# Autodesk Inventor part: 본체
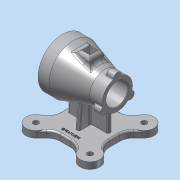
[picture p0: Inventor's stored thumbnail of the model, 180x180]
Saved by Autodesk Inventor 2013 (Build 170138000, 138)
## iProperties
Created: 2018-03
Part Number: 본체
Material: 알루미늄 6061
Document SubType Name: Modeling
Designer: dgall
Density: 2.71 g/cm^3
Mass: 1013.63 g
Surface Area: 870.735 cm^2
Volume: 374.034 cm^3
Author: dgall
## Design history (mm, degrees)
sketch "스케치1"
  geometry: L1 (0, 0)-(-68.205, 68.205); L2 (0, 0)-(-76.473, 0); L3 (-35.239, 60.483)-(-27.078, 52.322); L4 (-60.483, 35.239)-(-52.322, 27.078); L5 (-35.239, -60.483)-(-27.078, -52.322); L6 (-60.483, -35.239)-(-52.322, -27.078); L7 (0, 0)-(0, -76.473); L8 (0, 0)-(-68.205, -68.205); L9 (60.483, -35.239)-(52.322, -27.078); L10 (35.239, -60.483)-(27.078, -52.322); L11 (0, 0)-(76.473, 0); L12 (0, 0)-(68.205, -68.205); L13 (35.239, 60.483)-(27.078, 52.322); L14 (60.483, 35.239)-(52.322, 27.078); L15 (0, 0)-(0, 76.473); L16 (0, 0)-(68.205, 68.205); L17 (-9.4, 45)-(9.4, 45); L18 (32.068, 45)-(45, 45); L19 (45, 45)-(45, 32.068); L20 (45, 9.4)-(45, -9.4); L21 (45, -32.068)-(45, -45); L22 (45, -45)-(32.068, -45); L23 (9.4, -45)-(-9.4, -45); L24 (-32.068, -45)-(-45, -45); L25 (-45, -45)-(-45, -32.068); L26 (-45, -9.4)-(-45, 9.4); C1 r 5 at (-49.497, 49.497); C2 r 5 at (-49.497, -49.497); C3 r 5 at (49.497, -49.497); C4 r 5 at (49.497, 49.497); A1 r 18 centre (-49.497, 49.497) between (-35.239, 60.483) and (-60.483, 35.239); A2 r 25 centre (-9.4, 70) between (-27.078, 52.322) and (-9.4, 45); A3 r 25 centre (-70, 9.4) between (-45, 9.4) and (-52.322, 27.078); A4 r 18 centre (-49.497, -49.497) between (-60.483, -35.239) and (-35.239, -60.483); A5 r 25 centre (-70, -9.4) between (-52.322, -27.078) and (-45, -9.4); A6 r 25 centre (-9.4, -70) between (-9.4, -45) and (-27.078, -52.322); A7 r 18 centre (49.497, -49.497) between (35.239, -60.483) and (60.483, -35.239); A8 r 25 centre (9.4, -70) between (27.078, -52.322) and (9.4, -45); A9 r 25 centre (70, -9.4) between (45, -9.4) and (52.322, -27.078); A10 r 18 centre (49.497, 49.497) between (60.483, 35.239) and (35.239, 60.483); A11 r 25 centre (70, 9.4) between (52.322, 27.078) and (45, 9.4); A12 r 25 centre (9.4, 70) between (9.4, 45) and (27.078, 52.322); 5 further points
  constraints: 52 end point, 30 point on circle, 16 centre point, 13 parallel, 6 perpendicular, 6 tangent, 5 coincident, 4 horizontal, 4 point on line, 1 equal radius, 89 other
  dimensions: "d1" = 45 deg angle of L2 L1; "d2" = 10 diameter of C1; "d3" = 36 diameter of A1; "d4" = 90 distance of point (-45, 45) L18.end; "d5" = 90 distance of L18.end L21.end; "d6" = 25 radius of A2; "d9" = 360 deg dimension on point (0, 0) point (-45, 45) (derived)
extrude "돌출1" new body sketch "스케치1" distance "d11" = 12; taper "d12" = 0 deg
sketch "스케치2"
  geometry: L1 (-50, 82)-(50, 82); L2 (9.4, 0)-(27.078, 0) reference; L3 (0, 0)-(0, 110.069); L4 (-50, 127)-(-30, 127); L5 (-30, 127)-(27, 109.5); L6 (27, 109.5)-(50, 109.5); L7 (50, 109.5)-(50, 82); L8 (-50, 127)-(-50, 82)
  constraints: 14 end point, 2 parallel, 2 perpendicular, 1 horizontal
  dimensions: "d13" = 82 distance between parallel lines of L1 L2; "d14" = 50 distance from line of L4.start L3; "d15" = 20 distance of L4.start L4.end; "d16" = 77 horizontal distance of L5.end L4.start; "d17" = 100 horizontal distance of L4.start L6.end; "d19" = 90 diameter of L4 L1; "d21" = 55 diameter of L6 L1
revolve "회전1" sketch "스케치2" stored, may be unused: angle "d22" = 90 deg
sketch "스케치3"
  geometry: L1 (50, 54.5)-(50, 109.5) reference; L2 (50, 82)-(-50, 82); L3 (-50, 37)-(-50, 127) reference; L4 (-50, 82)-(-27, 82); L5 (-27, 82)-(-27, 117); L6 (-27, 117)-(-50, 117); L7 (-50, 117)-(-50, 82); L8 (-27, 82)-(20, 82); L9 (20, 82)-(20, 108); L10 (20, 108)-(-27, 108); L11 (-27, 108)-(-27, 82); L12 (20, 82)-(50, 82); L13 (50, 82)-(50, 102); L14 (50, 102)-(20, 102); L15 (20, 102)-(20, 82); 1 further point
  constraints: 26 end point, 6 parallel, 3 horizontal, 3 perpendicular, 2 midpoint, 1 point on line
  dimensions: "d23" = 23 distance of L5.end L6.end; "d25" = 47 distance of L9.end L10.end; "d26" = 30 distance of L13.end L14.end (derived); "d27" = 70 diameter of L6 L2; "d28" = 52 diameter of L10 L8; "d29" = 40 diameter of L14 L2
revolve "회전2" sketch "스케치3" stored, may be unused: angle "d30" = 90 deg
sketch "스케치4"
  geometry: L1 (0, 0)-(52.632, 0); C1 r 27.5 at (0, 0) reference; A1 r 27.5 centre (0, 0) between (27.5, 0) and (26.609, -6.943); A2 r 7 centre (27.5, 0) between (26.609, -6.943) and (26.609, 6.943); 1 further point
  constraints: 5 point on circle, 2 centre point, 2 end point, 1 coincident, 1 horizontal, 1 point on line
  dimensions: "d31" = 55 diameter of A1; "d32" = 14 diameter of A2
extrude "돌출2" join sketch "스케치4" distance "d33" = 15; taper "d34" = 0 deg
sketch "스케치5"
  geometry: A1 r 7 centre (0, 0) between (-0.891, -6.943) and (-0.891, 6.943) reference; 1 further point
hole "구멍1" sketch "스케치5" at (0, 0) diameter "d38" = 2.459; stored, may be unused: countersink angle "d42" = 90 deg, drill point angle "d44" = 118 deg; dims "d39" = 9, "d40" = 4, "d41" = 2, "d43" = 11
fillet "모깎기1" dims "d48" = 3
fillet "모깎기2" dims "d49" = 1
fillet "모깎기3" dims "d50" = 3
fillet "모깎기4" dims "d51" = 1
fillet "모깎기5" dims "d52" = 3
fillet "모깎기6" dims "d53" = 1
sketch "스케치6"
  geometry: L1 (9.4, 12)-(27.078, 12) reference; L2 (9.4, 12)-(-9.4, 12) reference; L3 (0, 12)-(-24, 12); L4 (-27.078, 12)-(-9.4, 12) reference; L5 (0, 82)-(0, 54.5); L6 (0, 54.5)-(0, 12); L7 (-24, 12)-(-19.566, 62.676); C1 r 20 at (0, 82) reference; C2 r 26 at (0, 82) reference; C3 r 26 at (0, 82) reference; A1 r 27.5 centre (0, 82) between (-19.566, 62.676) and (0, 54.5) reference; A2 r 45 centre (0, 82) between (0, 37) and (-21.342, 42.383) reference; 2 further points
  constraints: 8 end point, 4 point on circle, 3 point on line, 2 perpendicular, 1 coincident, 1 midpoint
  dimensions: "d54" = 24 distance of L3.start L3.end
extrude "돌출3" join sketch "스케치6" stored distance "d58" = 8; taper "d59" = 0 deg
sketch "스케치7"
  geometry: L1 (0, 0)-(0, 140.05); L2 (0, 0)-(-37, 0); L3 (-27.078, 0)-(-9.4, 0) reference; L4 (35.239, 0)-(27.078, 0) reference; L5 (-50, 37)-(-30, 37) reference; L6 (-30, 37)-(27, 54.5) reference; L7 (-37, 0)-(-37, 37); L8 (-37, 37)-(-30, 37); L9 (-4, 44.982)-(-4, 12); L10 (-4, 51.223)-(-4, 12) reference; L11 (-4, 12)-(-37, 12); L12 (0, 12.216)-(37, 12.216); L13 (9.4, 0)-(27.078, 0) reference; L14 (27, 54.5)-(50, 54.5) reference; L15 (27, 54.5)-(50, 54.5) reference; L16 (37, 12.216)-(37, 54.5); L17 (27, 54.5)-(-4, 44.982)
  constraints: 18 end point, 5 point on line, 4 collinear, 3 perpendicular, 1 parallel, 1 vertical
  dimensions: "d60" = 37 distance of L1.start L2.end; "d63" = 37 distance of L12.start L12.end
extrude "돌출4" join sketch "스케치7" stored distance "d61" = 8; taper "d62" = 0 deg
sketch "스케치8" dims "d64" = 80
  geometry: L1 (0, 0)-(-50.939, 0); C1 r 45 at (0, 0) reference; 2 further points
  constraints: 2 end point, 1 coincident, 1 horizontal, 1 horizontal alignment, 1 point on line, 2 other
hole "구멍2" sketch "스케치8" at (-40, 0) diameter "d65" = 3.242; stored, may be unused: countersink angle "d69" = 90 deg, drill point angle "d71" = 118 deg; dims "d66" = 9, "d67" = 4, "d68" = 2, "d70" = 11
chamfer "모따기1" distance "d75" = 1; stored, may be unused: second distance "d76" = 2, angle "d77" = 45 deg
chamfer "모따기2" distance "d78" = 1; stored, may be unused: second distance "d79" = 2, angle "d80" = 45 deg
fillet "모깎기7" dims "d81" = 3
fillet "모깎기8" dims "d82" = 3
fillet "모깎기9" dims "d83" = 3
fillet "모깎기10" dims "d84" = 3
fillet "모깎기11" dims "d85" = 3
fillet "모깎기12" dims "d86" = 3
fillet "모깎기13" dims "d87" = 3
fillet "모깎기14" dims "d88" = 3
fillet "모깎기15" dims "d89" = 3
fillet "모깎기16" dims "d90" = 3
fillet "모깎기17" dims "d91" = 3
fillet "모깎기18" dims "d92" = 3
fillet "모깎기19" dims "d93" = 3
sketch "스케치9"
  geometry: L1 (-45, 9.4)-(-45, -9.4) reference; 2 further points
  constraints: 1 other
  dimensions: "d94" = 45 distance from line of L1 point (0, 35); "d95" = 35 distance of point (0, 35) point (0, 0)
feature "엠보싱1" sketch "스케치9" dims "d9" = 360 deg (derived), "d96" = 0.5, "d97" = 0
node "작업 평면1"
sketch "스케치10"
  geometry: L1 (12.5, -12.5)-(-12.5, -12.5); L2 (-12.5, -12.5)-(-12.5, 12.5); L3 (-12.5, 12.5)-(12.5, 12.5); L4 (12.5, 12.5)-(12.5, -12.5); L5 (12.5, -12.5)-(-12.5, 12.5); L6 (-12.5, -12.5)-(12.5, 12.5); L7 (7.5, -7.5)-(-7.5, -7.5); L8 (-7.5, -7.5)-(-7.5, 7.5); L9 (-7.5, 7.5)-(7.5, 7.5); L10 (7.5, 7.5)-(7.5, -7.5); L11 (7.5, -7.5)-(-7.5, 7.5); L12 (-7.5, -7.5)-(7.5, 7.5); 1 further point
  constraints: 24 end point, 4 midpoint, 4 parallel, 2 horizontal, 2 perpendicular, 1 point on line
  dimensions: "d99" = 25 distance of L2.end L3.end; "d101" = 15 distance of L8.end L9.end; "d102" = 25 distance of L1.end L2.end; "d103" = 15 distance of L7.end L8.end (derived)
extrude "돌출5" join sketch "스케치10" stored distance "d104" = 10; taper "d105" = 0 deg
fillet "모깎기21" dims "d107" = 8
fillet "모깎기22" dims "d108" = 8
extrude "돌출6" cut sketch "스케치10" stored distance "d109" = 10; taper "d110" = 0 deg
node "솔리드1"
pattern_circular "원형 패턴1" dims angle "d36" = 360 deg
pattern_circular "원형 패턴2" dims angle "d46" = 360 deg
mirror "대칭1"
pattern_circular "원형 패턴3" dims angle "d73" = 360 deg
node "투영된 루프1"
node "투영된 루프2"
other parameters: "d56" = 95 deg, "d98" = 127
